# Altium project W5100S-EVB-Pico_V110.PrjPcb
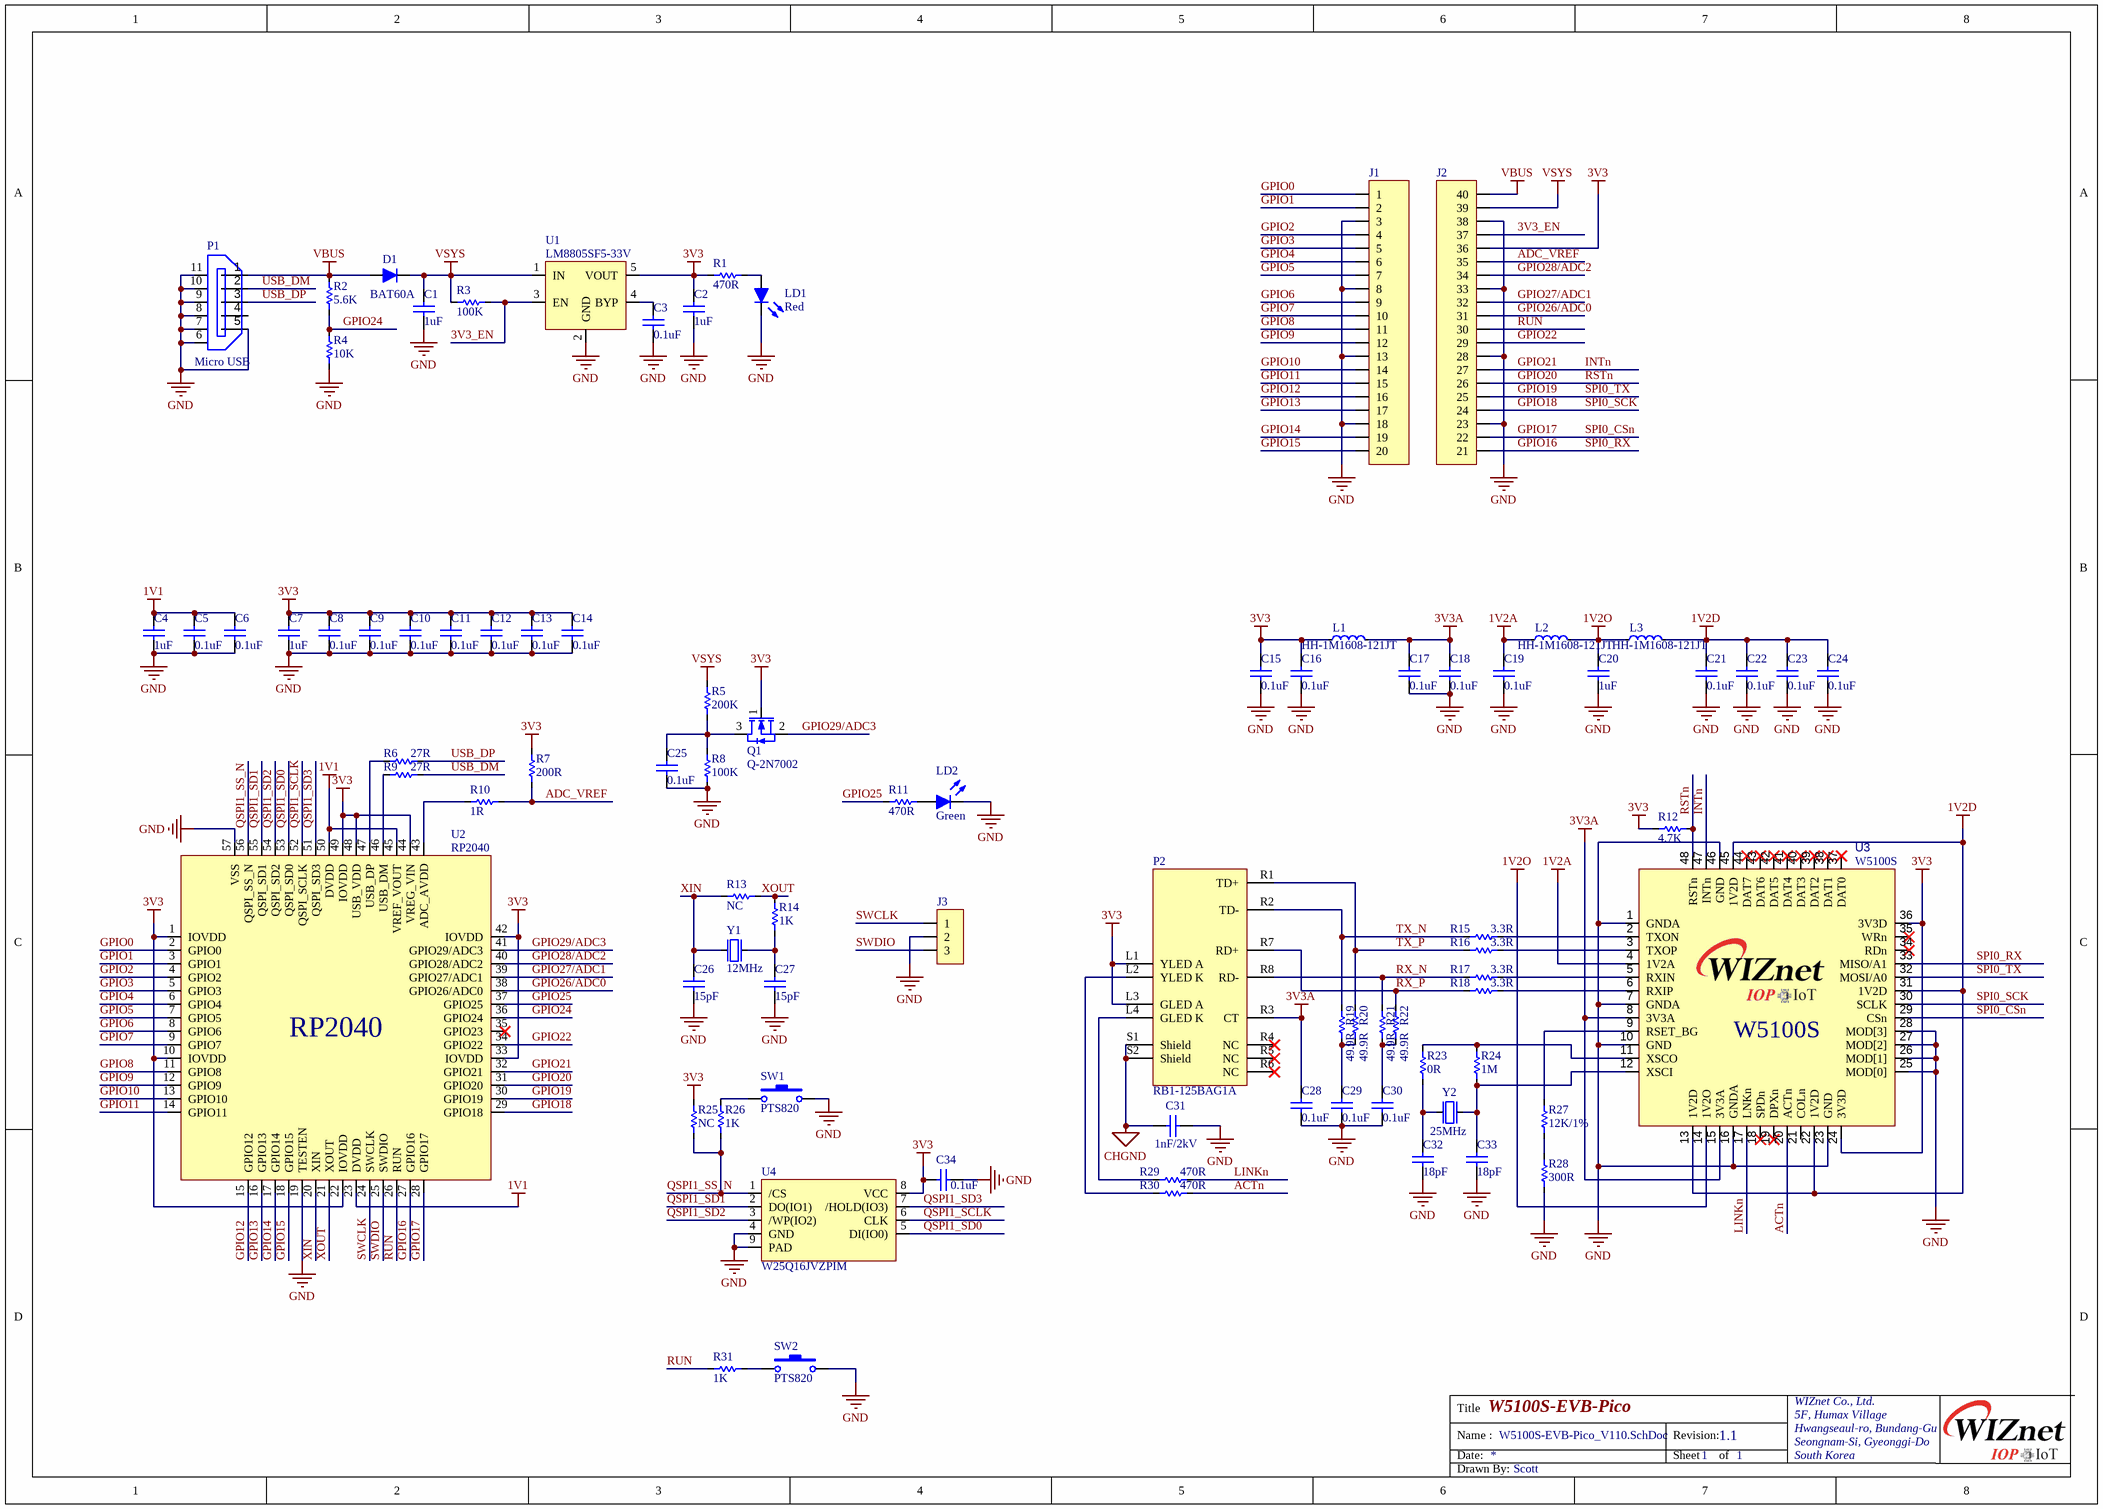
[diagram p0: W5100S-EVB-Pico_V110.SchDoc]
1 sheet, 85 parts. Net scope: global (net labels, ports and power ports of the same name join across sheets).
Board file: W5100S-EVB-Pico_V110.PcbDoc

## Sheet W5100S-EVB-Pico_V110.SchDoc: W5100S-EVB-Pico
size A3; DrawnBy: Scott; Organization: WIZnet Co., Ltd.; Address1: 5F, Humax Village; Address2: Hwangseaul-ro, Bundang-Gu; Address3: Seongnam-Si, Gyeonggi-Do; Address4: South Korea; Revision: 1.1; SheetNumber: 1; SheetTotal: 1

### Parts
C1  1uF  [CAP-0402]
C2  1uF  [CAP-0402]
C3  0.1uF  [CAP-0402]
C4  1uF  [CAP-0402]
C5  0.1uF  [CAP-0402]
C6  0.1uF  [CAP-0402]
C7  1uF  [CAP-0402]
C8  0.1uF  [CAP-0402]
C9  0.1uF  [CAP-0402]
C10  0.1uF  [CAP-0402]
C11  0.1uF  [CAP-0402]
C12  0.1uF  [CAP-0402]
C13  0.1uF  [CAP-0402]
C14  0.1uF  [CAP-0402]
C15  0.1uF  [CAP-0402]
C16  0.1uF  [CAP-0402]
C17  0.1uF  [CAP-0402]
C18  0.1uF  [CAP-0402]
C19  0.1uF  [CAP-0402]
C20  1uF  [CAP-0402]
C21  0.1uF  [CAP-0402]
C22  0.1uF  [CAP-0402]
C23  0.1uF  [CAP-0402]
C24  0.1uF  [CAP-0402]
C25  0.1uF  [CAP-0402]
C26  15pF  [CAP-0402]
C27  15pF  [CAP-0402]
C28  0.1uF  [CAP-0402]
C29  0.1uF  [CAP-0402]
C30  0.1uF  [CAP-0402]
C31  1nF/2kV  [CAP-1808]
C32  18pF  [CAP-0402]
C33  18pF  [CAP-0402]
C34  0.1uF  [CAP-0402]
D1  BAT60A  [SOD-323(1-C,2-A)]
J1  2.54mm 1x20 Pin Header DIP  [IDC-1X20]  (value not drawn)
J2  2.54mm 1x20 Pin Header DIP  [IDC-1X20]  (value not drawn)
J3  2.54mm 1x3 Pin Header DIP  [idc-1x3]  (value not drawn)
L1  HH-1M1608-121JT  [IND-0603]
L2  HH-1M1608-121JT  [IND-0603]
L3  HH-1M1608-121JT  [IND-0603]
LD1  Red  [LED-0603-RED]
LD2  Green  [LED-0603-green]
P1  Micro USB  [Micro 5P B DBX 6.4]
P2  RB1-125BAG1A  [RB1-125BAG1A]
Q1  Q-2N7002  [SOT23-3L]
R1  470R  [RES-0402]
R2  5.6K  [RES-0402]
R3  100K  [RES-0402]
R4  10K  [RES-0402]
R5  200K  [RES-0402]
R6  27R  [RES-0402]
R7  200R  [RES-0402]
R8  100K  [RES-0402]
R9  27R  [RES-0402]
R10  1R  [RES-0402]
R11  470R  [RES-0402]
R12  4.7K  [RES-0402]
R13  NC  [RES-0402]
R14  1K  [RES-0402]
R15  3.3R  [RES-0402]
R16  3.3R  [RES-0402]
R17  3.3R  [RES-0402]
R18  3.3R  [RES-0402]
R19  49.9R  [RES-0402]
R20  49.9R  [RES-0402]
R21  49.9R  [RES-0402]
R22  49.9R  [RES-0402]
R23  0R  [RES-0402]
R24  1M  [RES-0402]
R25  NC  [RES-0402]
R26  1K  [RES-0402]
R27  12K/1%  [RES-0402]
R28  300R  [RES-0402]
R29  470R  [RES-0402]
R30  470R  [RES-0402]
R31  1K  [RES-0402]
SW1  PTS820  [1185A]
SW2  PTS820  [1185A]
U1  LM8805SF5-33V  [SOT-23-5L]
U2  RP2040  [RP2040_QFN56(0.4/7X7)]
U3  W5100S  [W5100S_LQFP48(0.5/9.0)]
U4  W25Q16JVZPIM  [WSON8(6X5_1.27)]
Y1  12MHz  [OSC-TZ1067B]
Y2  25MHz  [OSC-82J0626]

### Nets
1V1: C4.2 C5.2 C6.2 U2.23(DVDD) U2.45(VREF_VOUT) U2.50(DVDD)
1V2A: C19.2 L2.1 U3.4(1V2A)
1V2D: C21.2 C22.2 C23.2 C24.2 L3.2 U3.13(1V2D) U3.22(1V2D) U3.31(1V2D) U3.45(1V2D)
1V2O: C20.2 L2.2 L3.1 U3.14(1V2O)
3V3: C2.2 C7.2 C8.2 C9.2 C10.2 C11.2 C12.2 C13.2 C14.2 C15.2 C16.2 C34.2 J2.16(36) L1.1 P2.L1(YLED_A) P2.L3(GLED_A) Q1.1(G) R1.1 R7.1 R12.1 R25.2 U1.5(VOUT) U2.1(IOVDD) U2.10(IOVDD) U2.22(IOVDD) U2.33(IOVDD) U2.42(IOVDD) U2.44(VREG_VIN) U2.48(USB_VDD) U2.49(IOVDD) U3.24(3V3D) U3.36(3V3D) U4.8(VCC)
3V3A: C17.2 C18.2 C28.2 L1.2 P2.R3(CT) U3.8(3V3A) U3.15(3V3A)
CHGND: C31.2 P2.S1(Shield) P2.S2(Shield)
GND: C1.1 C2.1 C3.1 C4.1 C5.1 C6.1 C7.1 C8.1 C9.1 C10.1 C11.1 C12.1 C13.1 C14.1 C15.1 C16.1 C17.1 C18.1 C19.1 C20.1 C21.1 C22.1 C23.1 C24.1 C25.2 C26.2 C27.2 C28.1 C29.1 C30.1 C31.1 C32.1 C33.1 C34.1 J1.3 J1.8 J1.13 J1.18 J2.3(23) J2.8(28) J2.13(33) J2.18(38) J3.2 LD1.2(K) LD2.2(K) P1.5 P1.6 P1.7 P1.8 P1.9 P1.10 P1.11 R4.1 R8.1 R28.2 SW1.2 SW2.2 U1.2(GND) U2.19(TESTEN) U2.57(VSS) U3.1(GNDA) U3.7(GNDA) U3.10(GND) U3.16(GNDA) U3.23(GND) U3.25(MOD[0]) U3.26(MOD[1]) U3.27(MOD[2]) U3.28(MOD[3]) U3.46(GND) U4.4(GND) U4.9(PAD) Y1.2 Y1.4 Y2.2(GND) Y2.4(GND)
VBUS: D1.2(A) J2.20(40) P1.1 R2.2
VSYS: C1.2 D1.1(K) J2.19(39) R3.1 R5.2 U1.1(IN)
3V3_EN: J2.17(37) R3.2 U1.3(EN)
ACTn: R30.2 U3.20(ACTn)
ADC_VREF: J2.15(35) R7.2 R10.2
GPIO0: J1.1 U2.2(GPIO0)
GPIO1: J1.2 U2.3(GPIO1)
GPIO2: J1.4 U2.4(GPIO2)
GPIO3: J1.5 U2.5(GPIO3)
GPIO4: J1.6 U2.6(GPIO4)
GPIO5: J1.7 U2.7(GPIO5)
GPIO6: J1.9 U2.8(GPIO6)
GPIO7: J1.10 U2.9(GPIO7)
GPIO8: J1.11 U2.11(GPIO8)
GPIO9: J1.12 U2.12(GPIO9)
GPIO10: J1.14 U2.13(GPIO10)
GPIO11: J1.15 U2.14(GPIO11)
GPIO12: J1.16 U2.15(GPIO12)
GPIO13: J1.17 U2.16(GPIO13)
GPIO14: J1.19 U2.17(GPIO14)
GPIO15: J1.20 U2.18(GPIO15)
GPIO16: J2.1(21) U2.27(GPIO16) U3.33(MISO/A1)  [also labelled SPI0_RX]
GPIO17: J2.2(22) U2.28(GPIO17) U3.29(CSn)  [also labelled SPI0_CSn]
GPIO18: J2.4(24) U2.29(GPIO18) U3.30(SCLK)  [also labelled SPI0_SCK]
GPIO19: J2.5(25) U2.30(GPIO19) U3.32(MOSI/A0)  [also labelled SPI0_TX]
GPIO20: J2.6(26) R12.2 U2.31(GPIO20) U3.48(RSTn)  [also labelled RSTn]
GPIO21: J2.7(27) U2.32(GPIO21) U3.47(INTn)  [also labelled INTn]
GPIO22: J2.9(29) U2.34(GPIO22)
GPIO24: R2.1 R4.2 U2.36(GPIO24)
GPIO25: R11.2 U2.37(GPIO25)
GPIO26/ADC0: J2.11(31) U2.38(GPIO26/ADC0)
GPIO27/ADC1: J2.12(32) U2.39(GPIO27/ADC1)
GPIO28/ADC2: J2.14(34) U2.40(GPIO28/ADC2)
GPIO29/ADC3: Q1.2(S) U2.41(GPIO29/ADC3)
LINKn: R29.2 U3.17(LNKn)
QSPI1_SCLK: U2.52(QSPI_SCLK) U4.6(CLK)
QSPI1_SD0: U2.53(QSPI_SD0) U4.5(DI(IO0))
QSPI1_SD1: U2.55(QSPI_SD1) U4.2(DO(IO1))
QSPI1_SD2: U2.54(QSPI_SD2) U4.3(/WP(IO2))
QSPI1_SD3: U2.51(QSPI_SD3) U4.7(/HOLD(IO3))
QSPI1_SS_N: R25.1 R26.1 U2.56(QSPI_SS_N) U4.1(/CS)
RUN: J2.10(30) R31.2 U2.26(RUN)
RX_N: P2.R8(RD-) R17.1 R21.2
RX_P: P2.R7(RD+) R18.1 R22.2
SWCLK: J3.1 U2.24(SWCLK)
SWDIO: J3.3 U2.25(SWDIO)
TX_N: P2.R2(TD-) R15.1 R19.2
TX_P: P2.R1(TD+) R16.1 R20.2
USB_DM: P1.2 R9.1
USB_DP: P1.3 R6.1
XIN: C26.1 R13.2 U2.20(XIN) Y1.1(inp)
XOUT: R13.1 R14.2 U2.21(XOUT)
NetC3_2: C3.2 U1.4(BYP)
NetC25_1: C25.1 Q1.3(D) R5.1 R8.2
NetC27_1: C27.1 R14.1 Y1.3(out)
NetC29_2: C29.2 R19.1 R20.1
NetC30_2: C30.2 R21.1 R22.1
NetC32_2: C32.2 R23.1 Y2.1(inp)
NetC33_2: C33.2 R24.1 U3.12(XSCI) Y2.3(out)
NetLD1_1: LD1.1(A) R1.2
NetLD2_1: LD2.1(A) R11.1
NetP2_L2: P2.L2(YLED_K) R30.1
NetP2_L4: P2.L4(GLED_K) R29.1
NetR6_2: R6.2 U2.47(USB_DP)
NetR9_2: R9.2 U2.46(USB_DM)
NetR10_1: R10.1 U2.43(ADC_AVDD)
NetR15_2: R15.2 U3.2(TXON)
NetR16_2: R16.2 U3.3(TXOP)
NetR17_2: R17.2 U3.5(RXIN)
NetR18_2: R18.2 U3.6(RXIP)
NetR23_2: R23.2 R24.2 U3.11(XSCO)
NetR26_2: R26.2 SW1.1
NetR27_1: R27.1 U3.9(RSET_BG)
NetR27_2: R27.2 R28.1
NetR31_1: R31.1 SW2.1

Not connected (* = marked no-connect by the designer): P1 4; P2 R4(NC)* R5(NC)* R6(NC)*; U2 35(GPIO23)*; U3 18(SPDn)* 19(DPXn)* 21(COLn) 34(RDn)* 35(WRn)* 37(DAT0)* 38(DAT1)* 39(DAT2)* 40(DAT3)* 41(DAT4)* 42(DAT5)* 43(DAT6)* 44(DAT7)*

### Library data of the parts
C1-C30 C32-C34 = CAP-0402: Ceramic CAP 0402(1005)
C31 = CAP-1808: Ceramic CAP 1808(4520)
D1 = DIODE-BAT60A: Silicon Schottky Diode
L1-L3 = IND-0603: Inductor 0603(1608)
LD1 LD2 = LED-0603
P1 = Micro USB 5P DBX6.4: Micro USB B Connector SMD
Q1 = Q-2N7002: N-Channel 60-V (D-S) MOSFET
R1-R31 = RES-0402
SW1 SW2 = ITS-1107(SMD): TACT Switch (SMD)
U1 = LM8805SF5-33V: 600mA CMOS LDO Regulator
U2 = RP2040: Raspverry Pi, Dual ARM Cortex-M0+ @ 133MHz
U3 = W5100S: WIZnet Hardwired TCP/IP Chip
U4 = W25Q16JVZPIM: 3V 16M-BIT / SERIAL FLASH MEMORY WITH / DUAL/QUAD SPI, QPI & DTR
Y1 = OSC-TZ1067B-12MHz: X-tal 12MHz,3.2x2.5 SMD, CL=20pF
Y2 = OSC-82J0626-25MHz: X-tal 25MHz,3.2x2.5 SMD, CL=18pF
